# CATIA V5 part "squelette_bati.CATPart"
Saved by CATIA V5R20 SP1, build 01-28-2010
Part number: squelette_bati
Publications: "LineForRevolute1", "LineForCylindrical", "PlaneForRevolute"
Bounding box of the stored display mesh (mm): x -10 to 10, y 10 to 500, z 0 to 0
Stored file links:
  C:\Users\Fox\Desktop\IAO Projet\A RENDRE\Sauvegarde IFMA\squelette_bati.CATPart
  C:\Users\Fox\Desktop\IAO Projet\A RENDRE\Sauvegarde IFMA\squelette.CATProduct
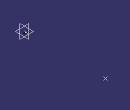
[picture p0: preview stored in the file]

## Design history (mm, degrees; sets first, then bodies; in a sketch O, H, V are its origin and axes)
Set1
  Point1: linked copy from another document
  Point2: linked copy from another document
  Plane1: linked copy from another document
Set2
  Line1: type Normal, RefPoint Point1, RefSkin Plane1, Start -10, End 10
Body1 (main body)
